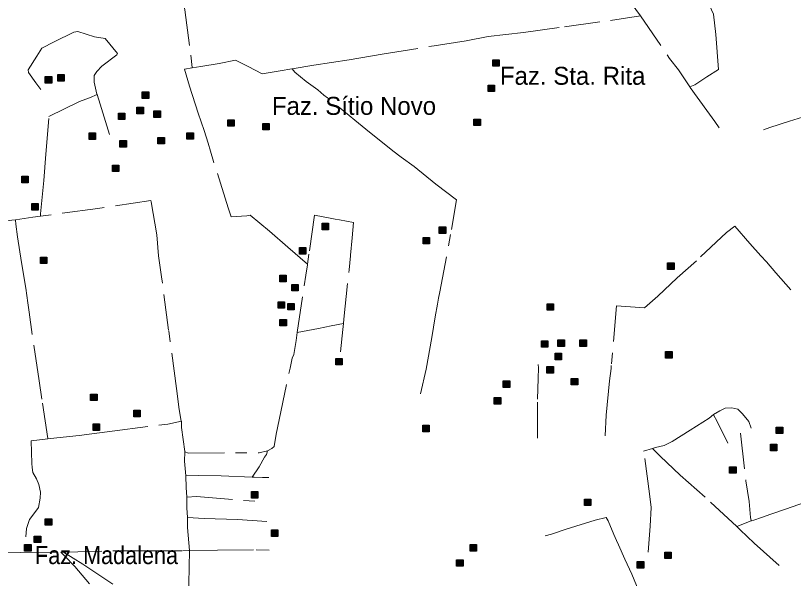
# Model space of a CAD drawing. Extents: x 393.5 to 446.9, y 8064.8 to 8120.4.
# Drawn here: x 405.95 to 412.88, y 8075.67 to 8080.69 of the extents above; entities that cross this region are included whole.
import ezdxf

# ---------------------------------------------------------------- set-up
doc = ezdxf.new("R2010")
doc.units = 0
doc.header["$LTSCALE"] = 0.064
doc.linetypes.add('DOT_DASHED', pattern=[7.7, 5, -1.2, 0.3, -1.2])
doc.layers.add('2', color=7, linetype='Continuous', lineweight=25)
doc.layers.add('22', color=7, linetype='DOT_DASHED', lineweight=13)
doc.layers.add('61', color=7, linetype='Continuous')

msp = doc.modelspace()

# ---------------------------------------------------------------- hatches: boundary and pattern name
at = {"layer": '2'}
for points in [[(410.2011, 8080.2955), (410.2591, 8080.2955), (410.2591, 8080.2375), (410.2011, 8080.2375)], [(406.2145, 8080.1449), (406.2725, 8080.1449), (406.2725, 8080.0869), (406.2145, 8080.0869)], [(406.3265, 8080.163), (406.3845, 8080.163), (406.3845, 8080.105), (406.3265, 8080.105)], [(410.1592, 8080.0705), (410.2172, 8080.0705), (410.2172, 8080.0125), (410.1592, 8080.0125)], [(407.0784, 8080.0084), (407.1364, 8080.0084), (407.1364, 8079.9504), (407.0784, 8079.9504)], [(407.0318, 8079.8718), (407.0898, 8079.8718), (407.0898, 8079.8138), (407.0318, 8079.8138)], [(407.1831, 8079.8394), (407.2411, 8079.8394), (407.2411, 8079.7814), (407.1831, 8079.7814)], [(406.8665, 8079.8209), (406.9245, 8079.8209), (406.9245, 8079.7629), (406.8665, 8079.7629)], [(407.841, 8079.7606), (407.899, 8079.7606), (407.899, 8079.7026), (407.841, 8079.7026)], [(410.0328, 8079.7661), (410.0908, 8079.7661), (410.0908, 8079.7081), (410.0328, 8079.7081)], [(408.1523, 8079.7286), (408.2103, 8079.7286), (408.2103, 8079.6706), (408.1523, 8079.6706)], [(406.6054, 8079.6441), (406.6634, 8079.6441), (406.6634, 8079.5861), (406.6054, 8079.5861)], [(407.4764, 8079.6444), (407.5344, 8079.6444), (407.5344, 8079.5864), (407.4764, 8079.5864)], [(406.8805, 8079.5749), (406.9385, 8079.5749), (406.9385, 8079.5169), (406.8805, 8079.5169)], [(407.2191, 8079.6036), (407.2771, 8079.6036), (407.2771, 8079.5456), (407.2191, 8079.5456)], [(406.8131, 8079.3563), (406.8711, 8079.3563), (406.8711, 8079.2983), (406.8131, 8079.2983)], [(406.0063, 8079.2568), (406.0643, 8079.2568), (406.0643, 8079.1988), (406.0063, 8079.1988)], [(406.095, 8079.0142), (406.153, 8079.0142), (406.153, 8078.9562), (406.095, 8078.9562)], [(408.6815, 8078.8384), (408.7395, 8078.8384), (408.7395, 8078.7804), (408.6815, 8078.7804)], [(409.7248, 8078.8063), (409.7828, 8078.8063), (409.7828, 8078.7483), (409.7248, 8078.7483)], [(409.5798, 8078.7119), (409.6378, 8078.7119), (409.6378, 8078.6539), (409.5798, 8078.6539)], [(408.4783, 8078.6207), (408.5363, 8078.6207), (408.5363, 8078.5627), (408.4783, 8078.5627)], [(406.1718, 8078.5369), (406.2298, 8078.5369), (406.2298, 8078.4789), (406.1718, 8078.4789)], [(411.7578, 8078.4852), (411.8158, 8078.4852), (411.8158, 8078.4272), (411.7578, 8078.4272)], [(408.3041, 8078.3752), (408.3621, 8078.3752), (408.3621, 8078.3172), (408.3041, 8078.3172)], [(408.4111, 8078.2932), (408.4691, 8078.2932), (408.4691, 8078.2352), (408.4111, 8078.2352)], [(408.2889, 8078.1389), (408.3469, 8078.1389), (408.3469, 8078.0809), (408.2889, 8078.0809)], [(408.375, 8078.124), (408.433, 8078.124), (408.433, 8078.066), (408.375, 8078.066)], [(410.6856, 8078.1205), (410.7436, 8078.1205), (410.7436, 8078.0625), (410.6856, 8078.0625)], [(408.3049, 8077.9817), (408.3629, 8077.9817), (408.3629, 8077.9237), (408.3049, 8077.9237)], [(410.6348, 8077.7913), (410.6928, 8077.7913), (410.6928, 8077.7333), (410.6348, 8077.7333)], [(410.7816, 8077.7986), (410.8396, 8077.7986), (410.8396, 8077.7406), (410.7816, 8077.7406)], [(410.9776, 8077.7989), (411.0356, 8077.7989), (411.0356, 8077.7409), (410.9776, 8077.7409)], [(410.7557, 8077.6788), (410.8137, 8077.6788), (410.8137, 8077.6208), (410.7557, 8077.6208)], [(411.7401, 8077.6944), (411.7981, 8077.6944), (411.7981, 8077.6364), (411.7401, 8077.6364)], [(408.8023, 8077.6342), (408.8603, 8077.6342), (408.8603, 8077.5762), (408.8023, 8077.5762)], [(410.6838, 8077.5604), (410.7418, 8077.5604), (410.7418, 8077.5024), (410.6838, 8077.5024)], [(410.2938, 8077.4336), (410.3518, 8077.4336), (410.3518, 8077.3756), (410.2938, 8077.3756)], [(410.9007, 8077.4557), (410.9587, 8077.4557), (410.9587, 8077.3977), (410.9007, 8077.3977)], [(406.6193, 8077.316), (406.6773, 8077.316), (406.6773, 8077.258), (406.6193, 8077.258)], [(410.2149, 8077.2851), (410.2729, 8077.2851), (410.2729, 8077.2271), (410.2149, 8077.2271)], [(407.0033, 8077.1711), (407.0613, 8077.1711), (407.0613, 8077.1131), (407.0033, 8077.1131)], [(406.6408, 8077.0498), (406.6988, 8077.0498), (406.6988, 8076.9918), (406.6408, 8076.9918)], [(409.5773, 8077.0382), (409.6353, 8077.0382), (409.6353, 8076.9802), (409.5773, 8076.9802)], [(412.7269, 8077.022), (412.7849, 8077.022), (412.7849, 8076.964), (412.7269, 8076.964)], [(412.6746, 8076.8679), (412.7326, 8076.8679), (412.7326, 8076.8099), (412.6746, 8076.8099)], [(412.3106, 8076.6685), (412.3686, 8076.6685), (412.3686, 8076.6105), (412.3106, 8076.6105)], [(408.052, 8076.4471), (408.11, 8076.4471), (408.11, 8076.3891), (408.052, 8076.3891)], [(411.0171, 8076.3803), (411.0751, 8076.3803), (411.0751, 8076.3223), (411.0171, 8076.3223)], [(406.2155, 8076.2046), (406.2735, 8076.2046), (406.2735, 8076.1466), (406.2155, 8076.1466)], [(408.2291, 8076.1052), (408.2871, 8076.1052), (408.2871, 8076.0472), (408.2291, 8076.0472)], [(406.1163, 8076.0505), (406.1743, 8076.0505), (406.1743, 8075.9925), (406.1163, 8075.9925)], [(406.0302, 8075.9745), (406.0882, 8075.9745), (406.0882, 8075.9165), (406.0302, 8075.9165)], [(409.9984, 8075.9745), (410.0564, 8075.9745), (410.0564, 8075.9165), (409.9984, 8075.9165)], [(411.7332, 8075.9068), (411.7912, 8075.9068), (411.7912, 8075.8488), (411.7332, 8075.8488)], [(409.8791, 8075.8387), (409.9371, 8075.8387), (409.9371, 8075.7807), (409.8791, 8075.7807)], [(411.4884, 8075.8219), (411.5464, 8075.8219), (411.5464, 8075.7639), (411.4884, 8075.7639)]]:
    msp.add_hatch(color=256, dxfattribs=at).paths.add_polyline_path(points)

# ---------------------------------------------------------------- linework, layer by layer
for points in [[(410.2011, 8080.2955), (410.2591, 8080.2955), (410.2591, 8080.2375), (410.2011, 8080.2375)], [(406.2145, 8080.1449), (406.2725, 8080.1449), (406.2725, 8080.0869), (406.2145, 8080.0869)], [(406.3265, 8080.163), (406.3845, 8080.163), (406.3845, 8080.105), (406.3265, 8080.105)], [(410.1592, 8080.0705), (410.2172, 8080.0705), (410.2172, 8080.0125), (410.1592, 8080.0125)], [(407.0784, 8080.0084), (407.1364, 8080.0084), (407.1364, 8079.9504), (407.0784, 8079.9504)], [(407.0318, 8079.8718), (407.0898, 8079.8718), (407.0898, 8079.8138), (407.0318, 8079.8138)], [(407.1831, 8079.8394), (407.2411, 8079.8394), (407.2411, 8079.7814), (407.1831, 8079.7814)], [(406.8665, 8079.8209), (406.9245, 8079.8209), (406.9245, 8079.7629), (406.8665, 8079.7629)], [(407.841, 8079.7606), (407.899, 8079.7606), (407.899, 8079.7026), (407.841, 8079.7026)], [(410.0328, 8079.7661), (410.0908, 8079.7661), (410.0908, 8079.7081), (410.0328, 8079.7081)], [(408.1523, 8079.7286), (408.2103, 8079.7286), (408.2103, 8079.6706), (408.1523, 8079.6706)], [(406.6054, 8079.6441), (406.6634, 8079.6441), (406.6634, 8079.5861), (406.6054, 8079.5861)], [(407.4764, 8079.6444), (407.5344, 8079.6444), (407.5344, 8079.5864), (407.4764, 8079.5864)], [(406.8805, 8079.5749), (406.9385, 8079.5749), (406.9385, 8079.5169), (406.8805, 8079.5169)], [(407.2191, 8079.6036), (407.2771, 8079.6036), (407.2771, 8079.5456), (407.2191, 8079.5456)], [(406.8131, 8079.3563), (406.8711, 8079.3563), (406.8711, 8079.2983), (406.8131, 8079.2983)], [(406.0063, 8079.2568), (406.0643, 8079.2568), (406.0643, 8079.1988), (406.0063, 8079.1988)], [(406.095, 8079.0142), (406.153, 8079.0142), (406.153, 8078.9562), (406.095, 8078.9562)], [(408.6815, 8078.8384), (408.7395, 8078.8384), (408.7395, 8078.7804), (408.6815, 8078.7804)], [(409.7248, 8078.8063), (409.7828, 8078.8063), (409.7828, 8078.7483), (409.7248, 8078.7483)], [(409.5798, 8078.7119), (409.6378, 8078.7119), (409.6378, 8078.6539), (409.5798, 8078.6539)], [(408.4783, 8078.6207), (408.5363, 8078.6207), (408.5363, 8078.5627), (408.4783, 8078.5627)], [(406.1718, 8078.5369), (406.2298, 8078.5369), (406.2298, 8078.4789), (406.1718, 8078.4789)], [(411.7578, 8078.4852), (411.8158, 8078.4852), (411.8158, 8078.4272), (411.7578, 8078.4272)], [(408.3041, 8078.3752), (408.3621, 8078.3752), (408.3621, 8078.3172), (408.3041, 8078.3172)], [(408.4111, 8078.2932), (408.4691, 8078.2932), (408.4691, 8078.2352), (408.4111, 8078.2352)], [(408.2889, 8078.1389), (408.3469, 8078.1389), (408.3469, 8078.0809), (408.2889, 8078.0809)], [(408.375, 8078.124), (408.433, 8078.124), (408.433, 8078.066), (408.375, 8078.066)], [(410.6856, 8078.1205), (410.7436, 8078.1205), (410.7436, 8078.0625), (410.6856, 8078.0625)], [(408.3049, 8077.9817), (408.3629, 8077.9817), (408.3629, 8077.9237), (408.3049, 8077.9237)], [(410.6348, 8077.7913), (410.6928, 8077.7913), (410.6928, 8077.7333), (410.6348, 8077.7333)], [(410.7816, 8077.7986), (410.8396, 8077.7986), (410.8396, 8077.7406), (410.7816, 8077.7406)], [(410.9776, 8077.7989), (411.0356, 8077.7989), (411.0356, 8077.7409), (410.9776, 8077.7409)], [(410.7557, 8077.6788), (410.8137, 8077.6788), (410.8137, 8077.6208), (410.7557, 8077.6208)], [(411.7401, 8077.6944), (411.7981, 8077.6944), (411.7981, 8077.6364), (411.7401, 8077.6364)], [(408.8023, 8077.6342), (408.8603, 8077.6342), (408.8603, 8077.5762), (408.8023, 8077.5762)], [(410.6838, 8077.5604), (410.7418, 8077.5604), (410.7418, 8077.5024), (410.6838, 8077.5024)], [(410.2938, 8077.4336), (410.3518, 8077.4336), (410.3518, 8077.3756), (410.2938, 8077.3756)], [(410.9007, 8077.4557), (410.9587, 8077.4557), (410.9587, 8077.3977), (410.9007, 8077.3977)], [(406.6193, 8077.316), (406.6773, 8077.316), (406.6773, 8077.258), (406.6193, 8077.258)], [(410.2149, 8077.2851), (410.2729, 8077.2851), (410.2729, 8077.2271), (410.2149, 8077.2271)], [(407.0033, 8077.1711), (407.0613, 8077.1711), (407.0613, 8077.1131), (407.0033, 8077.1131)], [(406.6408, 8077.0498), (406.6988, 8077.0498), (406.6988, 8076.9918), (406.6408, 8076.9918)], [(409.5773, 8077.0382), (409.6353, 8077.0382), (409.6353, 8076.9802), (409.5773, 8076.9802)], [(412.7269, 8077.022), (412.7849, 8077.022), (412.7849, 8076.964), (412.7269, 8076.964)], [(412.6746, 8076.8679), (412.7326, 8076.8679), (412.7326, 8076.8099), (412.6746, 8076.8099)], [(412.3106, 8076.6685), (412.3686, 8076.6685), (412.3686, 8076.6105), (412.3106, 8076.6105)], [(408.052, 8076.4471), (408.11, 8076.4471), (408.11, 8076.3891), (408.052, 8076.3891)], [(411.0171, 8076.3803), (411.0751, 8076.3803), (411.0751, 8076.3223), (411.0171, 8076.3223)], [(406.2155, 8076.2046), (406.2735, 8076.2046), (406.2735, 8076.1466), (406.2155, 8076.1466)], [(408.2291, 8076.1052), (408.2871, 8076.1052), (408.2871, 8076.0472), (408.2291, 8076.0472)], [(406.1163, 8076.0505), (406.1743, 8076.0505), (406.1743, 8075.9925), (406.1163, 8075.9925)], [(406.0302, 8075.9745), (406.0882, 8075.9745), (406.0882, 8075.9165), (406.0302, 8075.9165)], [(409.9984, 8075.9745), (410.0564, 8075.9745), (410.0564, 8075.9165), (409.9984, 8075.9165)], [(411.7332, 8075.9068), (411.7912, 8075.9068), (411.7912, 8075.8488), (411.7332, 8075.8488)], [(409.8791, 8075.8387), (409.9371, 8075.8387), (409.9371, 8075.7807), (409.8791, 8075.7807)], [(411.4884, 8075.8219), (411.5464, 8075.8219), (411.5464, 8075.7639), (411.4884, 8075.7639)]]:
    msp.add_lwpolyline(points, close=True, dxfattribs=at)
at = {"layer": '22'}
for p, q in [((408.4132, 8080.2146), (408.4129, 8080.2146)), ((411.9553, 8080.0552), (411.956, 8080.0542)), ((412.6122, 8079.6708), (412.6688, 8079.6918)), ((408.8712, 8077.9445), (408.8712, 8077.945)), ((406.2389, 8076.9181), (406.2387, 8076.9194)), ((408.1937, 8076.8088), (408.1941, 8076.809)), ((411.623, 8076.8301), (411.6251, 8076.8309))]:
    msp.add_line(p, q, dxfattribs=at)
for points in [[(406.5174, 8081.4192), (406.7191, 8081.3304), (407.1673, 8081.1187), (407.4176, 8081.0063), (407.4573, 8080.7392), (407.5106, 8080.3351), (407.5223, 8080.2251), (407.5224, 8080.2241), (407.5224, 8080.2237)], [(411.5161, 8080.6866), (411.3056, 8080.9805), (411.0311, 8081.3686), (410.9897, 8081.429), (410.9763, 8081.4422)], [(411.9553, 8080.0552), (412.0021, 8080.0713), (412.1074, 8080.1425), (412.2129, 8080.209), (412.1889, 8080.5219), (412.1659, 8080.7022), (412.131, 8080.7794), (412.1085, 8080.8293)], [(408.4132, 8080.2146), (408.6083, 8080.2459), (408.9233, 8080.2937), (409.2175, 8080.3457), (409.6798, 8080.421), (409.9657, 8080.4647), (410.1612, 8080.502), (410.4747, 8080.5399), (410.8387, 8080.5895), (411.2511, 8080.6457), (411.5161, 8080.6866)], [(411.5161, 8080.6866), (411.7766, 8080.3067), (411.8551, 8080.2044), (411.9553, 8080.0552)], [(406.8575, 8080.3523), (406.7476, 8080.4841), (406.6549, 8080.5013), (406.5039, 8080.5469), (406.4709, 8080.5406), (406.2948, 8080.4558), (406.1848, 8080.3977), (406.1407, 8080.3285), (406.0637, 8080.2044), (406.0653, 8080.1809), (406.1313, 8080.0897), (406.1761, 8080.03)], [(406.6756, 8079.9902), (406.6517, 8080.096), (406.6517, 8080.1557), (406.6742, 8080.1918), (406.7198, 8080.2389), (406.8519, 8080.3395), (406.8575, 8080.3523)], [(408.4129, 8080.2146), (408.3086, 8080.198), (408.148, 8080.1711), (408.0224, 8080.2348), (407.9111, 8080.2925), (407.7628, 8080.2617), (407.6021, 8080.2351), (407.5224, 8080.2237)], [(407.5224, 8080.2237), (407.4542, 8080.2111), (407.5008, 8080.0605)], [(408.6971, 8079.9796), (408.6429, 8080.0282), (408.5392, 8080.1022), (408.4391, 8080.184), (408.4132, 8080.2146)], [(407.5008, 8080.0605), (407.5761, 8079.8203), (407.6299, 8079.6661), (407.6658, 8079.5513), (407.6872, 8079.4819), (407.6874, 8079.4814)], [(411.956, 8080.0542), (411.9595, 8080.0489), (412.1089, 8079.8427), (412.179, 8079.745), (412.2187, 8079.6901)], [(406.1723, 8078.9003), (406.1742, 8078.9218), (406.2037, 8079.2206), (406.2191, 8079.4526), (406.2481, 8079.7904), (406.5216, 8079.9224), (406.6081, 8079.9569), (406.6767, 8079.9855)], [(406.7872, 8079.6295), (406.7055, 8079.9002), (406.6767, 8079.9855), (406.6756, 8079.9902)], [(409.3862, 8079.4278), (409.3118, 8079.4837), (409.0699, 8079.6758), (408.7301, 8079.9559), (408.6971, 8079.9796)], [(412.6688, 8079.6918), (412.8452, 8079.7468), (413.3033, 8079.8923), (413.3327, 8079.9089)], [(408.0106, 8078.9057), (407.8704, 8078.8951), (407.8443, 8078.9758), (407.7143, 8079.3882), (407.6874, 8079.4814)], [(409.7188, 8078.1704), (409.7298, 8078.2256), (409.8344, 8078.7817), (409.8773, 8079.0484), (409.693, 8079.1865), (409.5005, 8079.3443), (409.3862, 8079.4278)], [(407.2227, 8078.5479), (407.2091, 8078.7353), (407.1593, 8079.0304), (407.1562, 8079.0397), (406.6837, 8078.9698), (406.1723, 8078.9003)], [(405.2075, 8078.7664), (405.2789, 8078.7819), (405.7836, 8078.846), (405.917, 8078.8654), (405.951, 8078.8695)], [(406.1723, 8078.9003), (406.1045, 8078.8911), (405.951, 8078.8695)], [(406.2387, 8076.9194), (406.1857, 8077.2705), (406.16, 8077.4337), (406.0999, 8077.8477), (406.072, 8078.0454), (406.0591, 8078.128), (406.042, 8078.2603), (406.0034, 8078.4881), (405.969, 8078.7178), (405.9516, 8078.8308), (405.951, 8078.867), (405.951, 8078.8695)], [(408.551, 8078.4748), (408.3756, 8078.6261), (408.2113, 8078.7678), (408.0401, 8078.9094), (408.0106, 8078.9057)], [(408.7977, 8078.8744), (408.7522, 8078.8843), (408.614, 8078.9094), (408.5641, 8078.5613), (408.551, 8078.4748), (408.5501, 8078.4686)], [(408.9336, 8078.5478), (408.9341, 8078.5531), (408.9486, 8078.7088), (408.9621, 8078.8448), (408.8347, 8078.8699), (408.7977, 8078.8744)], [(412.5901, 8078.5469), (412.49, 8078.6571), (412.3571, 8078.8131), (412.2841, 8078.7567), (412.0159, 8078.5046), (411.8424, 8078.352), (411.6714, 8078.1878), (411.5535, 8078.0849), (411.3028, 8078.1031), (411.2572, 8077.5695), (411.2551, 8077.5449)], [(407.4268, 8077.0747), (407.4069, 8077.1781), (407.3842, 8077.3639), (407.3138, 8077.8866), (407.2502, 8078.3614), (407.2227, 8078.5479)], [(408.8712, 8077.945), (408.8742, 8077.982), (408.9208, 8078.4222), (408.9336, 8078.5478)], [(412.8552, 8078.244), (412.7236, 8078.3958), (412.6381, 8078.4949), (412.5901, 8078.5469)], [(408.458, 8077.8649), (408.5367, 8078.3744), (408.5501, 8078.4686)], [(409.5581, 8077.3164), (409.6075, 8077.539), (409.6575, 8077.8213), (409.6879, 8078.0037), (409.7097, 8078.1166), (409.7188, 8078.1704)], [(408.458, 8077.8649), (408.6477, 8077.9), (408.7626, 8077.9234), (408.8712, 8077.9445)], [(408.845, 8077.6908), (408.8649, 8077.8911), (408.8712, 8077.9445)], [(408.1941, 8076.809), (408.2323, 8076.8291), (408.2548, 8076.8493), (408.2728, 8076.9593), (408.2997, 8077.0872), (408.3952, 8077.5458), (408.4131, 8077.6354), (408.4293, 8077.6677), (408.44, 8077.7394), (408.449, 8077.7939), (408.4578, 8077.8634), (408.458, 8077.8649)], [(410.5991, 8076.9229), (410.6011, 8077.27), (410.6053, 8077.4534), (410.6075, 8077.5487), (410.6049, 8077.5804)], [(411.2551, 8077.5449), (411.2409, 8077.4351), (411.2108, 8077.1267), (411.2015, 8076.942)], [(412.1667, 8077.1323), (412.2234, 8077.1661), (412.2708, 8077.1898), (412.3317, 8077.1932), (412.3842, 8077.1813), (412.4265, 8077.1407), (412.4823, 8077.0714), (412.5026, 8077.0122)], [(411.6251, 8076.8309), (411.6501, 8076.8403), (411.7267, 8076.8584), (411.7977, 8076.8922), (411.9602, 8076.9953), (412.1286, 8077.1001), (412.1667, 8077.1323)], [(412.2963, 8076.877), (412.1989, 8077.0714), (412.1679, 8077.13), (412.1679, 8077.1301), (412.1667, 8077.1323)], [(406.2389, 8076.9181), (406.3187, 8076.9248), (406.5163, 8076.9473), (406.8106, 8076.9854), (407.3059, 8077.0483), (407.4272, 8077.073)], [(407.4272, 8077.073), (407.4271, 8077.0734), (407.4268, 8077.0747)], [(407.4272, 8077.073), (407.4294, 8077.0191), (407.459, 8076.8046), (407.4597, 8076.7999)], [(412.5043, 8076.1872), (412.528, 8076.1922), (412.594, 8076.2159), (412.6786, 8076.2447), (412.8095, 8076.2886), (413.3443, 8076.4776), (413.5626, 8076.552), (413.6371, 8076.5774), (413.6371, 8076.6044), (413.5728, 8076.7076), (413.4213, 8076.9325), (413.3233, 8077.0882)], [(406.0964, 8076.6974), (406.0884, 8076.8979), (406.2389, 8076.9181)], [(412.4063, 8076.9676), (412.4557, 8076.5415), (412.4861, 8076.3573), (412.4975, 8076.2142), (412.5041, 8076.1879), (412.5043, 8076.1872)], [(407.4683, 8076.5881), (407.4552, 8076.7191), (407.4597, 8076.7999)], [(407.4597, 8076.7999), (407.4911, 8076.7887), (408.12, 8076.7932), (408.1937, 8076.8088), (408.1942, 8076.8089)], [(408.1694, 8076.7528), (408.1852, 8076.7775), (408.1937, 8076.8088)], [(411.5856, 8075.9054), (411.6018, 8076.1397), (411.6115, 8076.3039), (411.5978, 8076.4254), (411.5452, 8076.8081), (411.623, 8076.8301)], [(412.3744, 8076.134), (412.0935, 8076.3972), (411.8701, 8076.5917), (411.6933, 8076.7608), (411.623, 8076.8301)], [(408.0572, 8076.5763), (408.12, 8076.6675), (408.1694, 8076.7528)], [(406.0429, 8076.0437), (406.0493, 8076.1182), (406.0741, 8076.1967), (406.1325, 8076.273), (406.1549, 8076.3045), (406.1706, 8076.3875), (406.1729, 8076.4414), (406.1572, 8076.5087), (406.1369, 8076.5603), (406.1055, 8076.6164), (406.0988, 8076.6613), (406.0964, 8076.6974)], [(407.4682, 8076.5881), (407.581, 8076.5889), (407.7809, 8076.5867), (408.0572, 8076.5763)], [(407.4762, 8076.3968), (407.4707, 8076.4827), (407.4683, 8076.5867), (407.4683, 8076.5881)], [(408.0572, 8076.5763), (408.0774, 8076.5755), (408.1515, 8076.5732), (408.2076, 8076.571)], [(407.4762, 8076.3968), (407.4756, 8076.3003), (407.4823, 8076.215)], [(407.4762, 8076.3968), (407.5632, 8076.4013), (408.1808, 8076.3519)], [(407.4823, 8076.215), (407.6305, 8076.206), (407.927, 8076.197), (408.1898, 8076.1813)], [(407.4823, 8076.215), (407.4823, 8076.1252), (407.5, 8075.9203)], [(411.3212, 8075.9705), (411.3044, 8076.0116), (411.2801, 8076.0647), (411.2299, 8076.1847), (411.2102, 8076.2166), (411.1144, 8076.1923), (410.8545, 8076.1118), (410.7238, 8076.0678), (410.6676, 8076.051)], [(412.3744, 8076.134), (412.5034, 8076.1868), (412.5043, 8076.1872)], [(412.3744, 8076.134), (412.4056, 8076.1055), (412.5297, 8075.9876), (412.7531, 8075.788)], [(411.5036, 8075.5604), (411.4384, 8075.7091), (411.3761, 8075.844), (411.3212, 8075.9705)], [(405.7894, 8075.9053), (405.9912, 8075.9023), (406.3547, 8075.906), (406.3767, 8075.9062)], [(407.2086, 8074.9506), (406.9878, 8075.1969), (406.6096, 8075.6251), (406.4774, 8075.7783), (406.3878, 8075.8726), (406.3547, 8075.906)], [(406.3767, 8075.9062), (406.55, 8075.7986), (407.0193, 8075.4844), (407.2546, 8075.3272), (407.3091, 8075.2993)], [(406.3768, 8075.9062), (406.3987, 8075.9063), (406.8325, 8075.9192), (407.1106, 8075.9192), (407.4362, 8075.9193), (407.4938, 8075.9202), (407.5, 8075.9203)], [(407.494, 8075.5289), (407.4939, 8075.6244), (407.5, 8075.9203)], [(407.5, 8075.9203), (407.7493, 8075.9239), (408.0952, 8075.9264), (408.2102, 8075.9245)]]:
    msp.add_lwpolyline(points, dxfattribs=at)

# ---------------------------------------------------------------- texts
at = {"layer": '61'}
for s, p in [('Faz. Sta. Rita', (410.2645, 8080.0725)), ('Faz. Sítio Novo', (408.2337, 8079.8044))]:
    msp.add_text(s, height=0.16, dxfattribs=at).set_placement(p)
at = {"layer": '61', "width": 0.9}
msp.add_text('Faz. Madalena', height=0.16, dxfattribs=at).set_placement((406.124, 8075.8001))

doc.saveas('drawing.dxf')
